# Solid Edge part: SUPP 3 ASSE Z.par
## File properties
Subject: SUPP 3 ASSE Z
Author: f_grande
Template: Normal.par
Last saved by: f_grande
Revision: 15
Application: Solid Edge
Material: MDF
Stile della faccia: Marroncino
Coef. of Thermal Exp: 0.0
Thermal Conductivity: 0.0
Specific Heat: 0.0
Modulus of Elasticity: 0.0
Poisson's Ratio: 0.0
Yield Stress: 0.0
Ultimate Stress: 0.0
Elongation: 0.0
Tipo di contenuto documento: 0
Densità: 750,000 kg/m^3
Precisione: 0,990
Document Number: KR0142
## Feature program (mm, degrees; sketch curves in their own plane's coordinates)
sketch for "unnamed Protrusion 1" plane through (0, 0, 0) normal (0, -1, 0) x-axis (1, 0, 0)
  line (-62.6034, 28.5859) -> (62.3966, 28.5859)
  line (62.3966, 28.5859) -> (62.3966, 9.5859)
  line (62.3966, 9.5859) -> (20.3966, 9.5859)
  line (-20.6034, 9.5859) -> (20.3966, 9.5859)
  line (-62.6034, 9.5859) -> (-20.6034, 9.5859)
  line (-62.6034, 28.5859) -> (-62.6034, 9.5859)
  dimension (linear) = 62.6034
  dimension (linear) = 62.6034
extrude "unnamed Protrusion 1" add finite 70 along +normal
sketch for "ExtrudedCutout_1" plane through (-0.1034, -70, 2.0859) normal (0, -1, 0) x-axis (0, 0, -1)
  circle centre (3.6, 0) radius 14
extrude "ExtrudedCutout_1" cut finite 132.7026 along -normal
sketch for "ExtrudedCutout_2" plane through (-0.1034, -70, 2.0859) normal (0, -1, 0) x-axis (0, 0, -1)
  line (27.5, 20.5) -> (27.5, -20.5)
  line (27.5, -20.5) -> (-26.5, -20.5)
  line (-26.5, -20.5) -> (-26.5, 20.5)
  line (-26.5, 20.5) -> (27.5, 20.5)
extrude "ExtrudedCutout_2" cut finite 10 along -normal
sketch for "Foro_1" plane through (-0.1034, -35, 28.5859) normal (0, 0, 1) x-axis (-1, 0, 0)
  hole centre (-26.5, 25.05) bore radius 2
hole "Foro_1" diameter 4 through
sketch for "unnamed Hole 1" plane through (-0.1034, -35, 28.5859) normal (0, 0, 1) x-axis (-1, 0, 0)
  hole centre (-26.5, -24.95) bore radius 2
hole "unnamed Hole 1" through
sketch for "unnamed Hole 2" plane through (-0.1034, -35, 28.5859) normal (0, 0, 1) x-axis (-1, 0, 0)
  hole centre (-56.5, -24.95) bore radius 2
hole "unnamed Hole 2" through
sketch for "unnamed Hole 3" plane through (-0.1034, -35, 28.5859) normal (0, 0, 1) x-axis (-1, 0, 0)
  hole centre (26.5, 25.05) bore radius 2
hole "unnamed Hole 3" through
sketch for "unnamed Hole 4" plane through (-0.1034, -35, 28.5859) normal (0, 0, 1) x-axis (-1, 0, 0)
  hole centre (56.5, 25.05) bore radius 2
hole "unnamed Hole 4" through
sketch for "unnamed Hole 5" plane through (-0.1034, -35, 28.5859) normal (0, 0, 1) x-axis (-1, 0, 0)
  hole centre (26.5, -24.95) bore radius 2
hole "unnamed Hole 5" through
sketch for "unnamed Hole 6" plane through (-0.1034, -35, 28.5859) normal (0, 0, 1) x-axis (-1, 0, 0)
  hole centre (56.5, -24.95) bore radius 2
hole "unnamed Hole 6" through
sketch for "unnamed Hole 7" plane through (-0.1034, -35, 28.5859) normal (0, 0, 1) x-axis (-1, 0, 0)
  hole centre (-56.5, 25.05) bore radius 2
hole "unnamed Hole 7" through
pattern "unnamed Pattern 1" of "Foro_1", "unnamed Hole 1", "unnamed Hole 2", "unnamed Hole 3", "unnamed Hole 4", "unnamed Hole 5", "unnamed Hole 6", "unnamed Hole 7"
sketch for "ExtrudedCutout_3" plane through (-0.1034, -35, 28.5859) normal (0, 0, 1) x-axis (-1, 0, 0)
extrude "ExtrudedCutout_3" cut finite 2 along -normal
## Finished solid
Body 1: solid body, 22 faces, 52 edges, 24 vertices.
  Faces by surface: plane 13, cylinder 9
  Edges by curve: line 34, circle 18
Bounding box of the edges (mm): 125.000 x 70.000 x 19.000, from (-62.6034, -70, 9.5859) to (62.3966, 0, 28.5859).
Cylindrical faces by radius (mm): R2 x8, R14 x1
Planar faces by outward normal: +x 2, +y 1, +z 3, -x 2, -y 3, -z 2
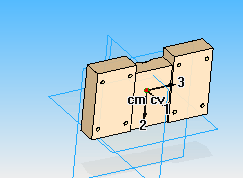
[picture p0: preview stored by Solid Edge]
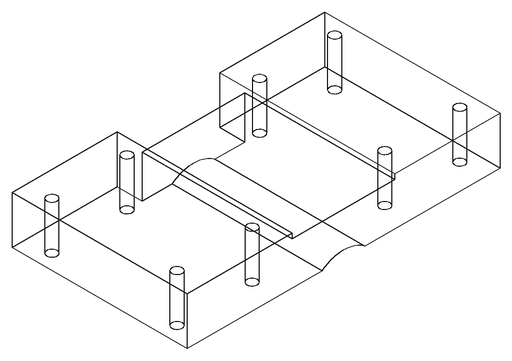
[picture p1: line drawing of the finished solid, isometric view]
